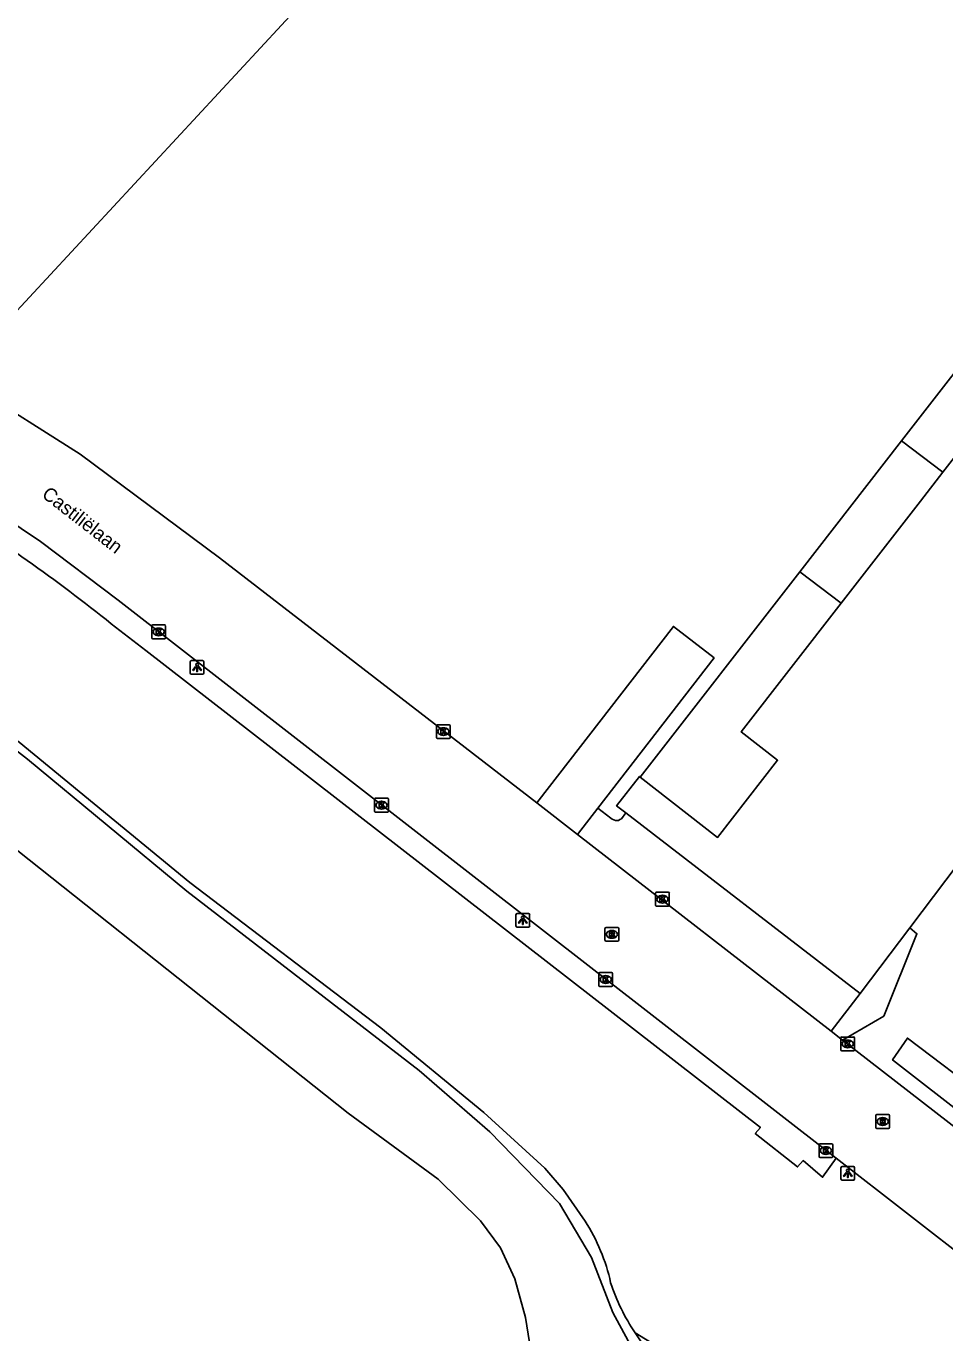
# Model space of a CAD drawing. Extents: x 159451 to 160663, y 388402 to 389723.
# Drawn here: x 160162.2 to 160229.1, y 389283.5 to 389378.7 of the extents above; entities that cross this region are included whole.
import ezdxf

# ---------------------------------------------------------------- set-up
doc = ezdxf.new("R2010")
doc.units = 0
for name, color, linetype in [('IMGEO_Groenvoorziening', 7, 'Continuous'), ('IMGEO_Kolk', 7, 'Continuous'), ('IMGEO_Lichtpunt', 7, 'Continuous'), ('IMGEO_Loofbos', 7, 'Continuous'), ('IMGEO_Meer_plas_ven_vijver', 7, 'Continuous'), ('IMGEO_Openbare_ruimte_label', 7, 'Continuous'), ('IMGEO_Pand', 7, 'Continuous'), ('IMGEO_Parkeervlak_onverhard', 7, 'Continuous'), ('IMGEO_Rijbaan_lokaal_gesloten', 7, 'Continuous'), ('IMGEO_Rijbaan_lokaal_open', 7, 'Continuous'), ('IMGEO_Rioolput', 7, 'Continuous'), ('IMGEO_Voetpad_open', 7, 'Continuous')]:
    doc.layers.add(name, color=color, linetype=linetype)

msp = doc.modelspace()

# ---------------------------------------------------------------- linework, layer by layer
at = {"layer": 'IMGEO_Groenvoorziening'}
for points in [[(160405.312, 389464.945), (160351.633, 389481.358), (160342.649, 389466.76), (160292.237, 389495.345), (160260.802, 389462.929), (160193.043, 389391.963), (160160.932, 389357.287)], [(160045.506, 389350.697), (160046.472, 389350.945), (160060.477, 389353.565), (160067.144, 389354.512), (160076.551, 389355.226), (160085.488, 389355.117), (160092.549, 389354.568), (160100.295, 389353.487), (160106.524, 389352.351), (160119.77, 389349.046), (160128.496, 389345.996), (160138.333, 389341.838), (160146.634, 389337.264), (160151.806, 389333.778), (160161.693, 389326.541), (160174.127, 389316.332), (160188.045, 389305.739), (160195.541, 389299.578), (160199.998, 389295.525), (160201.333, 389293.979), (160202.925, 389291.679)], [(160205.887, 389321.394), (160205.223, 389321.905), (160206.897, 389324.038), (160206.952, 389323.994)]]:
    msp.add_lwpolyline(points, dxfattribs=at)
for centre, radius, start, end in [((160191.555, 389284.326), 13.541, 12.21042, 32.88967), ((160218.692, 389291.721), 14.623, 198.05089, 214.03303)]:
    msp.add_arc(centre, radius, start, end, dxfattribs=at)
at = {"layer": 'IMGEO_Kolk'}
for p, q in [((160171.366, 389334.141), (160171.366, 389334.993)), ((160171.441, 389335.067), (160172.293, 389335.067)), ((160171.854, 389334.847), (160171.879, 389334.847)), ((160172.367, 389334.993), (160172.367, 389334.141)), ((160172.293, 389334.067), (160171.441, 389334.067)), ((160171.877, 389334.287), (160171.852, 389334.287)), ((160192.107, 389326.882), (160192.107, 389327.734)), ((160192.182, 389327.808), (160193.034, 389327.808)), ((160192.618, 389327.028), (160192.593, 389327.028)), ((160192.595, 389327.588), (160192.62, 389327.588)), ((160193.108, 389327.734), (160193.108, 389326.882)), ((160193.034, 389326.808), (160192.182, 389326.808)), ((160187.598, 389321.524), (160187.598, 389322.376)), ((160187.673, 389322.45), (160188.525, 389322.45)), ((160188.599, 389322.376), (160188.599, 389321.524)), ((160188.525, 389321.45), (160187.673, 389321.45)), ((160188.109, 389321.67), (160188.084, 389321.67)), ((160188.086, 389322.23), (160188.111, 389322.23)), ((160208.064, 389314.682), (160208.064, 389315.534)), ((160208.139, 389315.608), (160208.991, 389315.608)), ((160208.575, 389314.828), (160208.55, 389314.828)), ((160208.552, 389315.388), (160208.577, 389315.388)), ((160209.065, 389315.534), (160209.065, 389314.682)), ((160208.991, 389314.608), (160208.139, 389314.608)), ((160203.928, 389308.835), (160203.928, 389309.687)), ((160204.003, 389309.761), (160204.855, 389309.761)), ((160204.439, 389308.981), (160204.414, 389308.981)), ((160204.416, 389309.541), (160204.441, 389309.541)), ((160204.929, 389309.687), (160204.929, 389308.835)), ((160204.855, 389308.761), (160204.003, 389308.761)), ((160221.557, 389304.148), (160221.557, 389305)), ((160221.632, 389305.074), (160222.484, 389305.074)), ((160222.068, 389304.294), (160222.043, 389304.294)), ((160222.045, 389304.854), (160222.07, 389304.854)), ((160222.558, 389305), (160222.558, 389304.148)), ((160222.484, 389304.074), (160221.632, 389304.074)), ((160219.969, 389296.381), (160219.969, 389297.233)), ((160220.044, 389297.307), (160220.896, 389297.307)), ((160220.457, 389297.087), (160220.482, 389297.087)), ((160220.97, 389297.233), (160220.97, 389296.381)), ((160220.896, 389296.307), (160220.044, 389296.307)), ((160220.48, 389296.527), (160220.455, 389296.527))]:
    msp.add_line(p, q, dxfattribs=at)
for points in [[(160171.366, 389334.141), (160171.366, 389334.993)], [(160171.441, 389335.067), (160172.293, 389335.067)], [(160171.687, 389334.767), (160171.81, 389334.767), (160171.81, 389334.616), (160171.94, 389334.767), (160172.104, 389334.767), (160171.958, 389334.616), (160172.111, 389334.367), (160171.959, 389334.367), (160171.874, 389334.531), (160171.81, 389334.464), (160171.81, 389334.367), (160171.687, 389334.367), (160171.687, 389334.767)], [(160172.367, 389334.993), (160172.367, 389334.141)], [(160172.293, 389334.067), (160171.441, 389334.067)], [(160192.107, 389326.882), (160192.107, 389327.734)], [(160192.182, 389327.808), (160193.034, 389327.808)], [(160192.428, 389327.508), (160192.551, 389327.508), (160192.551, 389327.357), (160192.681, 389327.508), (160192.845, 389327.508), (160192.699, 389327.357), (160192.852, 389327.108), (160192.7, 389327.108), (160192.615, 389327.272), (160192.551, 389327.205), (160192.551, 389327.108), (160192.428, 389327.108), (160192.428, 389327.508)], [(160193.108, 389327.734), (160193.108, 389326.882)], [(160193.034, 389326.808), (160192.182, 389326.808)], [(160187.598, 389321.524), (160187.598, 389322.376)], [(160187.673, 389322.45), (160188.525, 389322.45)], [(160188.599, 389322.376), (160188.599, 389321.524)], [(160188.525, 389321.45), (160187.673, 389321.45)], [(160187.919, 389322.15), (160188.042, 389322.15), (160188.042, 389321.999), (160188.172, 389322.15), (160188.336, 389322.15), (160188.19, 389321.999), (160188.343, 389321.75), (160188.191, 389321.75), (160188.106, 389321.914), (160188.042, 389321.847), (160188.042, 389321.75), (160187.919, 389321.75), (160187.919, 389322.15)], [(160208.064, 389314.682), (160208.064, 389315.534)], [(160208.139, 389315.608), (160208.991, 389315.608)], [(160208.385, 389315.308), (160208.508, 389315.308), (160208.508, 389315.157), (160208.638, 389315.308), (160208.802, 389315.308), (160208.656, 389315.157), (160208.809, 389314.908), (160208.657, 389314.908), (160208.572, 389315.072), (160208.508, 389315.005), (160208.508, 389314.908), (160208.385, 389314.908), (160208.385, 389315.308)], [(160209.065, 389315.534), (160209.065, 389314.682)], [(160208.991, 389314.608), (160208.139, 389314.608)], [(160203.928, 389308.835), (160203.928, 389309.687)], [(160204.003, 389309.761), (160204.855, 389309.761)], [(160204.249, 389309.461), (160204.372, 389309.461), (160204.372, 389309.31), (160204.502, 389309.461), (160204.666, 389309.461), (160204.52, 389309.31), (160204.673, 389309.061), (160204.521, 389309.061), (160204.436, 389309.225), (160204.372, 389309.158), (160204.372, 389309.061), (160204.249, 389309.061), (160204.249, 389309.461)], [(160204.929, 389309.687), (160204.929, 389308.835)], [(160204.855, 389308.761), (160204.003, 389308.761)], [(160221.557, 389304.148), (160221.557, 389305)], [(160221.632, 389305.074), (160222.484, 389305.074)], [(160221.878, 389304.774), (160222.001, 389304.774), (160222.001, 389304.623), (160222.131, 389304.774), (160222.295, 389304.774), (160222.149, 389304.623), (160222.302, 389304.374), (160222.15, 389304.374), (160222.065, 389304.538), (160222.001, 389304.471), (160222.001, 389304.374), (160221.878, 389304.374), (160221.878, 389304.774)], [(160222.558, 389305), (160222.558, 389304.148)], [(160222.484, 389304.074), (160221.632, 389304.074)], [(160219.969, 389296.381), (160219.969, 389297.233)], [(160220.044, 389297.307), (160220.896, 389297.307)], [(160220.29, 389297.007), (160220.413, 389297.007), (160220.413, 389296.856), (160220.543, 389297.007), (160220.707, 389297.007), (160220.561, 389296.856), (160220.714, 389296.607), (160220.562, 389296.607), (160220.477, 389296.771), (160220.413, 389296.704), (160220.413, 389296.607), (160220.29, 389296.607), (160220.29, 389297.007)], [(160220.97, 389297.233), (160220.97, 389296.381)], [(160220.896, 389296.307), (160220.044, 389296.307)]]:
    msp.add_lwpolyline(points, dxfattribs=at)
for centre, start, end in [((160171.443, 389334.991), 91.55205, 178.44795), ((160171.443, 389334.991), 91.55205, 178.44795), ((160172.291, 389334.991), 1.55205, 88.44795), ((160172.291, 389334.991), 1.55205, 88.44795), ((160171.443, 389334.143), 181.55205, 268.44795), ((160171.443, 389334.143), 181.55205, 268.44795), ((160172.291, 389334.143), 271.55205, 358.44795), ((160172.291, 389334.143), 271.55205, 358.44795), ((160192.184, 389327.732), 91.55205, 178.44795), ((160192.184, 389327.732), 91.55205, 178.44795), ((160193.032, 389327.732), 1.55205, 88.44795), ((160193.032, 389327.732), 1.55205, 88.44795), ((160192.184, 389326.884), 181.55205, 268.44795), ((160192.184, 389326.884), 181.55205, 268.44795), ((160193.032, 389326.884), 271.55205, 358.44795), ((160193.032, 389326.884), 271.55205, 358.44795), ((160187.675, 389322.374), 91.55205, 178.44795), ((160187.675, 389322.374), 91.55205, 178.44795), ((160188.523, 389322.374), 1.55205, 88.44795), ((160188.523, 389322.374), 1.55205, 88.44795), ((160187.675, 389321.526), 181.55205, 268.44795), ((160187.675, 389321.526), 181.55205, 268.44795), ((160188.523, 389321.526), 271.55205, 358.44795), ((160188.523, 389321.526), 271.55205, 358.44795), ((160208.141, 389315.532), 91.55205, 178.44795), ((160208.141, 389315.532), 91.55205, 178.44795), ((160208.141, 389314.684), 181.55205, 268.44795), ((160208.141, 389314.684), 181.55205, 268.44795), ((160208.989, 389315.532), 1.55205, 88.44795), ((160208.989, 389315.532), 1.55205, 88.44795), ((160208.989, 389314.684), 271.55205, 358.44795), ((160208.989, 389314.684), 271.55205, 358.44795), ((160204.005, 389309.685), 91.55205, 178.44795), ((160204.005, 389309.685), 91.55205, 178.44795), ((160204.853, 389309.685), 1.55205, 88.44795), ((160204.853, 389309.685), 1.55205, 88.44795), ((160204.005, 389308.837), 181.55205, 268.44795), ((160204.005, 389308.837), 181.55205, 268.44795), ((160204.853, 389308.837), 271.55205, 358.44795), ((160204.853, 389308.837), 271.55205, 358.44795), ((160221.634, 389304.998), 91.55205, 178.44795), ((160221.634, 389304.998), 91.55205, 178.44795), ((160222.482, 389304.998), 1.55205, 88.44795), ((160222.482, 389304.998), 1.55205, 88.44795), ((160221.634, 389304.15), 181.55205, 268.44795), ((160221.634, 389304.15), 181.55205, 268.44795), ((160222.482, 389304.15), 271.55205, 358.44795), ((160222.482, 389304.15), 271.55205, 358.44795), ((160220.046, 389297.231), 91.55205, 178.44795), ((160220.046, 389297.231), 91.55205, 178.44795), ((160220.894, 389297.231), 1.55205, 88.44795), ((160220.894, 389297.231), 1.55205, 88.44795), ((160220.046, 389296.383), 181.55205, 268.44795), ((160220.046, 389296.383), 181.55205, 268.44795), ((160220.894, 389296.383), 271.55205, 358.44795), ((160220.894, 389296.383), 271.55205, 358.44795)]:
    msp.add_arc(centre, 0.0765, start, end, dxfattribs=at)
for centre, major_axis, ratio, start_param, end_param in [((160171.853, 389334.567), (-0.387, 0.002), 0.722429, 4.712389, 7.853982), ((160171.878, 389334.567), (-0.39, 0.002), 0.717154, 1.570796, 4.712389), ((160192.594, 389327.308), (-0.387, 0.002), 0.722429, 4.712389, 7.853982), ((160192.619, 389327.308), (-0.39, 0.002), 0.717154, 1.570796, 4.712389), ((160188.085, 389321.95), (-0.387, 0.002), 0.722429, 4.712389, 7.853982), ((160188.11, 389321.95), (-0.39, 0.002), 0.717154, 1.570796, 4.712389), ((160208.551, 389315.108), (-0.387, 0.002), 0.722429, 4.712389, 7.853982), ((160208.576, 389315.108), (-0.39, 0.002), 0.717154, 1.570796, 4.712389), ((160204.415, 389309.261), (-0.387, 0.002), 0.722429, 4.712389, 7.853982), ((160204.44, 389309.261), (-0.39, 0.002), 0.717154, 1.570796, 4.712389), ((160222.044, 389304.574), (-0.387, 0.002), 0.722429, 4.712389, 7.853982), ((160222.069, 389304.574), (-0.39, 0.002), 0.717154, 1.570796, 4.712389), ((160220.456, 389296.807), (-0.387, 0.002), 0.722429, 4.712389, 7.853982), ((160220.481, 389296.807), (-0.39, 0.002), 0.717154, 1.570796, 4.712389)]:
    msp.add_ellipse(centre, major_axis=major_axis, ratio=ratio, start_param=start_param, end_param=end_param, dxfattribs=at)
at = {"layer": 'IMGEO_Lichtpunt'}
for p, q in [((160174.167, 389332.378), (160174.167, 389331.571)), ((160174.167, 389332.378), (160174.167, 389331.571)), ((160175.069, 389332.473), (160174.261, 389332.473)), ((160175.069, 389332.473), (160174.261, 389332.473)), ((160175.163, 389331.571), (160175.163, 389332.378)), ((160175.163, 389331.571), (160175.163, 389332.378)), ((160174.261, 389331.477), (160175.069, 389331.477)), ((160174.261, 389331.477), (160175.069, 389331.477)), ((160197.895, 389313.976), (160197.895, 389313.169)), ((160197.895, 389313.976), (160197.895, 389313.169)), ((160198.797, 389314.071), (160197.989, 389314.071)), ((160198.797, 389314.071), (160197.989, 389314.071)), ((160198.891, 389313.169), (160198.891, 389313.976)), ((160198.891, 389313.169), (160198.891, 389313.976)), ((160197.989, 389313.075), (160198.797, 389313.075)), ((160197.989, 389313.075), (160198.797, 389313.075)), ((160222.47, 389295.646), (160221.662, 389295.646)), ((160222.47, 389295.646), (160221.662, 389295.646)), ((160221.568, 389295.551), (160221.568, 389294.744)), ((160221.568, 389295.551), (160221.568, 389294.744)), ((160222.564, 389294.744), (160222.564, 389295.551)), ((160222.564, 389294.744), (160222.564, 389295.551)), ((160221.662, 389294.65), (160222.47, 389294.65)), ((160221.662, 389294.65), (160222.47, 389294.65))]:
    msp.add_line(p, q, dxfattribs=at)
for points in [[(160174.541, 389332.042), (160174.58, 389332.014), (160174.392, 389331.752), (160174.354, 389331.779), (160174.541, 389332.042)], [(160174.643, 389331.994), (160174.69, 389331.994), (160174.69, 389331.672), (160174.643, 389331.672), (160174.643, 389331.994)], [(160174.753, 389332.014), (160174.791, 389332.041), (160174.978, 389331.779), (160174.939, 389331.751), (160174.753, 389332.014)], [(160198.269, 389313.64), (160198.308, 389313.612), (160198.12, 389313.35), (160198.082, 389313.377), (160198.269, 389313.64)], [(160198.371, 389313.592), (160198.418, 389313.592), (160198.418, 389313.27), (160198.371, 389313.27), (160198.371, 389313.592)], [(160198.481, 389313.612), (160198.519, 389313.639), (160198.706, 389313.377), (160198.667, 389313.349), (160198.481, 389313.612)], [(160221.942, 389295.215), (160221.981, 389295.187), (160221.793, 389294.925), (160221.755, 389294.952), (160221.942, 389295.215)], [(160222.044, 389295.167), (160222.091, 389295.167), (160222.091, 389294.845), (160222.044, 389294.845), (160222.044, 389295.167)], [(160222.154, 389295.187), (160222.192, 389295.214), (160222.379, 389294.952), (160222.34, 389294.924), (160222.154, 389295.187)]]:
    msp.add_lwpolyline(points, dxfattribs=at)
for centre in [(160174.666, 389332.176), (160198.394, 389313.774), (160222.067, 389295.349)]:
    msp.add_circle(centre, 0.0994, dxfattribs=at)
for centre, start, end in [((160174.261, 389332.378), 90, 180), ((160174.261, 389332.378), 90, 180), ((160175.069, 389332.378), 0, 90), ((160175.069, 389332.378), 0, 90), ((160174.261, 389331.571), 180, 270), ((160174.261, 389331.571), 180, 270), ((160175.069, 389331.571), 270, 0), ((160175.069, 389331.571), 270, 360), ((160197.989, 389313.976), 90, 180), ((160197.989, 389313.976), 90, 180), ((160198.797, 389313.976), 0, 90), ((160198.797, 389313.976), 0, 90), ((160197.989, 389313.169), 180, 270), ((160197.989, 389313.169), 180, 270), ((160198.797, 389313.169), 270, 0), ((160198.797, 389313.169), 270, 360), ((160221.662, 389295.551), 90, 180), ((160221.662, 389295.551), 90, 180), ((160222.47, 389295.551), 0, 90), ((160222.47, 389295.551), 0, 90), ((160221.662, 389294.744), 180, 270), ((160221.662, 389294.744), 180, 270), ((160222.47, 389294.744), 270, 0), ((160222.47, 389294.744), 270, 360)]:
    msp.add_arc(centre, 0.0946, start, end, dxfattribs=at)
at = {"layer": 'IMGEO_Loofbos'}
for points in [[(160206.574, 389283.537), (160209.191, 389279.606), (160221.192, 389262.816)], [(160206.574, 389283.537), (160243.218, 389261.098)]]:
    msp.add_lwpolyline(points, dxfattribs=at)
at = {"layer": 'IMGEO_Meer_plas_ven_vijver'}
for points in [[(160092.919, 389353.533), (160100.926, 389352.394), (160107.655, 389351.183), (160112.583, 389350.053), (160122.767, 389347.237), (160127.963, 389345.311), (160132.961, 389343.203), (160138.645, 389340.561), (160149.721, 389334.336), (160156.422, 389329.867), (160162.304, 389325.288), (160173.914, 389315.691), (160190.853, 389302.629), (160195.995, 389298.183), (160201.064, 389292.957), (160203.401, 389289.023), (160204.94, 389285.02), (160206.386, 389282.376), (160208.435, 389279.279), (160214.982, 389270.209), (160217.782, 389266.04), (160220.168, 389262.103)], [(160198.972, 389282.241), (160198.588, 389284.656), (160197.82, 389287.467), (160196.759, 389289.715), (160195.3, 389291.699), (160192.223, 389294.734), (160185.668, 389299.538), (160152.498, 389325.837)]]:
    msp.add_lwpolyline(points, dxfattribs=at)
at = {"layer": 'IMGEO_Pand'}
for points in [[(160225.978, 389348.463), (160233.375, 389357.976)], [(160236.382, 389355.697), (160238.8, 389353.864), (160238.691, 389353.723), (160236.032, 389350.278), (160233.602, 389352.12), (160228.984, 389346.184)], [(160218.568, 389338.933), (160225.978, 389348.463)], [(160225.978, 389348.463), (160228.984, 389346.184)], [(160228.984, 389346.184), (160227.35, 389344.083), (160221.58, 389336.65)], [(160206.952, 389323.994), (160218.568, 389338.933)], [(160221.58, 389336.65), (160218.568, 389338.933)], [(160221.58, 389336.65), (160214.309, 389327.282), (160216.954, 389325.219), (160212.581, 389319.604), (160206.952, 389323.994)]]:
    msp.add_lwpolyline(points, dxfattribs=at)
at = {"layer": 'IMGEO_Parkeervlak_onverhard'}
for points in [[(160203.854, 389321.727), (160204.8, 389320.995), (160204.904, 389320.933), (160205.011, 389320.879), (160205.145, 389320.835), (160205.29, 389320.828), (160205.359, 389320.844), (160205.467, 389320.896), (160205.571, 389320.964), (160205.887, 389321.394)], [(160205.887, 389321.394), (160222.965, 389308.25)]]:
    msp.add_lwpolyline(points, dxfattribs=at)
at = {"layer": 'IMGEO_Rijbaan_lokaal_gesloten'}
for points in [[(160221.208, 389296.259), (160168.905, 389336.87), (160163.263, 389341.138), (160159.079, 389343.943), (160154.522, 389346.754), (160149.935, 389349.372), (160143.566, 389352.728), (160139.509, 389354.6), (160132.569, 389357.472), (160125.562, 389359.985), (160123.157, 389360.753), (160116.579, 389362.625), (160109.896, 389364.162), (160108.024, 389364.594), (160102.576, 389365.527), (160096.479, 389366.433), (160089.122, 389367.059)], [(160158.016, 389352.63), (160158.238, 389352.505), (160166.141, 389347.496), (160176.29, 389339.963), (160199.403, 389322.122)], [(160199.403, 389322.122), (160209.358, 389334.965), (160212.327, 389332.665), (160203.854, 389321.727)], [(160199.403, 389322.122), (160202.38, 389319.824)], [(160202.38, 389319.824), (160203.854, 389321.727)], [(160202.38, 389319.824), (160220.844, 389305.497)], [(160221.683, 389304.846), (160224.683, 389306.599), (160227.106, 389312.595), (160226.576, 389313.019)], [(160222.965, 389308.25), (160226.576, 389313.019)], [(160220.844, 389305.497), (160222.965, 389308.25)], [(160220.844, 389305.497), (160221.683, 389304.846)], [(160221.683, 389304.846), (160230.418, 389298.069)], [(160257.092, 389268.396), (160221.208, 389296.259)]]:
    msp.add_lwpolyline(points, dxfattribs=at)
at = {"layer": 'IMGEO_Rijbaan_lokaal_open'}
for points in [[(160226.576, 389313.019), (160236.107, 389325.609), (160236.177, 389325.556), (160238.847, 389328.967), (160243.484, 389334.891), (160243.372, 389334.978), (160250.651, 389344.357), (160255.583, 389350.804), (160257.913, 389353.812), (160265.574, 389363.375), (160266.336, 389364.408), (160268.888, 389367.734), (160272.434, 389372.3), (160272.913, 389372.913), (160280.146, 389382.15), (160280.302, 389382.026), (160280.395, 389382.14), (160280.908, 389381.729), (160288.208, 389390.941), (160290.898, 389388.775), (160291.124, 389388.595)], [(160230.418, 389298.069), (160231.098, 389298.924), (160225.329, 389303.409), (160226.413, 389304.998), (160232.307, 389300.513)]]:
    msp.add_lwpolyline(points, dxfattribs=at)
at = {"layer": 'IMGEO_Rioolput'}
for p, q in [((160204.379, 389312.12), (160204.379, 389312.972)), ((160204.454, 389313.046), (160205.306, 389313.046)), ((160204.867, 389312.826), (160204.892, 389312.826)), ((160205.38, 389312.972), (160205.38, 389312.12)), ((160205.306, 389312.046), (160204.454, 389312.046)), ((160204.89, 389312.266), (160204.865, 389312.266)), ((160224.106, 389298.497), (160224.106, 389299.349)), ((160224.181, 389299.423), (160225.033, 389299.423)), ((160224.617, 389298.643), (160224.592, 389298.643)), ((160224.594, 389299.203), (160224.619, 389299.203)), ((160225.107, 389299.349), (160225.107, 389298.497)), ((160225.033, 389298.423), (160224.181, 389298.423))]:
    msp.add_line(p, q, dxfattribs=at)
for points in [[(160204.379, 389312.12), (160204.379, 389312.972)], [(160204.454, 389313.046), (160205.306, 389313.046)], [(160205.38, 389312.972), (160205.38, 389312.12)], [(160205.306, 389312.046), (160204.454, 389312.046)], [(160204.968, 389312.744), (160204.716, 389312.746), (160204.716, 389312.346)], [(160204.716, 389312.346), (160204.84, 389312.346), (160204.84, 389312.508), (160204.851, 389312.508)], [(160204.894, 389312.665), (160204.84, 389312.665), (160204.84, 389312.584)], [(160204.84, 389312.584), (160204.892, 389312.584)], [(160204.898, 389312.479), (160204.969, 389312.346), (160205.109, 389312.346), (160205.044, 389312.472)], [(160224.106, 389298.497), (160224.106, 389299.349)], [(160224.181, 389299.423), (160225.033, 389299.423)], [(160224.695, 389299.121), (160224.443, 389299.123), (160224.443, 389298.723)], [(160224.443, 389298.723), (160224.567, 389298.723), (160224.567, 389298.885), (160224.578, 389298.885)], [(160224.621, 389299.042), (160224.567, 389299.042), (160224.567, 389298.961)], [(160224.567, 389298.961), (160224.619, 389298.961)], [(160224.625, 389298.856), (160224.696, 389298.723), (160224.836, 389298.723), (160224.771, 389298.849)], [(160225.107, 389299.349), (160225.107, 389298.497)], [(160225.033, 389298.423), (160224.181, 389298.423)]]:
    msp.add_lwpolyline(points, dxfattribs=at)
for centre, radius, start, end in [((160204.456, 389312.97), 0.0765, 91.55205, 178.44795), ((160204.456, 389312.97), 0.0765, 91.55205, 178.44795), ((160205.304, 389312.97), 0.0765, 1.55205, 88.44795), ((160205.304, 389312.97), 0.0765, 1.55205, 88.44795), ((160204.456, 389312.122), 0.0765, 181.55205, 268.44795), ((160204.456, 389312.122), 0.0765, 181.55205, 268.44795), ((160204.85, 389312.455), 0.0533, 26.02933, 88.69889), ((160204.876, 389312.773), 0.19, 274.7715, 282.96867), ((160204.9, 389312.569), 0.0964, 77.00612, 93.18647), ((160204.914, 389312.626), 0.0378, 276.66336, 79.67722), ((160204.967, 389312.634), 0.109, 350.36119, 89.41601), ((160204.965, 389312.634), 0.112, 277.58423, 350.98172), ((160204.949, 389312.419), 0.108, 29.51342, 73.79051), ((160205.304, 389312.122), 0.0765, 271.55205, 358.44795), ((160205.304, 389312.122), 0.0765, 271.55205, 358.44795), ((160224.183, 389299.347), 0.0765, 91.55205, 178.44795), ((160224.183, 389299.347), 0.0765, 91.55205, 178.44795), ((160224.183, 389298.499), 0.0765, 181.55205, 268.44795), ((160224.183, 389298.499), 0.0765, 181.55205, 268.44795), ((160224.577, 389298.832), 0.0533, 26.02933, 88.69889), ((160224.603, 389299.15), 0.19, 274.7715, 282.96867), ((160224.627, 389298.946), 0.0964, 77.00612, 93.18647), ((160224.641, 389299.003), 0.0378, 276.66336, 79.67722), ((160224.694, 389299.011), 0.109, 350.36119, 89.41601), ((160224.692, 389299.011), 0.112, 277.58423, 350.98172), ((160224.676, 389298.796), 0.108, 29.51342, 73.79051), ((160225.031, 389299.347), 0.0765, 1.55205, 88.44795), ((160225.031, 389299.347), 0.0765, 1.55205, 88.44795), ((160225.031, 389298.499), 0.0765, 271.55205, 358.44795), ((160225.031, 389298.499), 0.0765, 271.55205, 358.44795)]:
    msp.add_arc(centre, radius, start, end, dxfattribs=at)
for centre, major_axis, ratio, start_param, end_param in [((160204.866, 389312.546), (-0.387, 0.002), 0.722429, 4.712389, 7.853982), ((160204.891, 389312.546), (-0.39, 0.002), 0.717154, 1.570796, 4.712389), ((160224.593, 389298.923), (-0.387, 0.002), 0.722429, 4.712389, 7.853982), ((160224.618, 389298.923), (-0.39, 0.002), 0.717154, 1.570796, 4.712389)]:
    msp.add_ellipse(centre, major_axis=major_axis, ratio=ratio, start_param=start_param, end_param=end_param, dxfattribs=at)
at = {"layer": 'IMGEO_Voetpad_open'}
msp.add_lwpolyline([(160221.208, 389296.259), (160220.228, 389294.868), (160218.806, 389296.075), (160218.402, 389295.619), (160215.327, 389298.05), (160215.702, 389298.491), (160170.928, 389333.22), (160168.404, 389335.154)], dxfattribs=at)
msp.add_arc((160097.271, 389247.24), 113.087, 51.02304, 58.78252, dxfattribs=at)

# ---------------------------------------------------------------- texts
at = {"layer": 'IMGEO_Openbare_ruimte_label'}
msp.add_text('Castiliëlaan', height=1, rotation=322.19035, dxfattribs=at).set_placement((160163.284, 389344.437))

doc.saveas('drawing.dxf')
